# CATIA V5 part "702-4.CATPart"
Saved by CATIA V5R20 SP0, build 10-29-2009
Part number: 702-4
Source: Unknown
Property "ARTICLENO": "702-4"
Property "BOMINFO": "702-4"
Property "CODE": "702-4"
Property "L": "120.000"
Property "LINA": "702-4"
Property "NB": "702-4"
Property "NBSYN": "$CODE."
Property "NN": "702"
Property "SUPPLIER": "CF"
Bounding box of the stored display mesh (mm): x -107 to 0, y 0 to 120, z -15 to 15
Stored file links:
  C:\Users\Utente\Desktop\3D files 702\702-4.CATPart
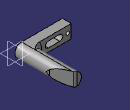
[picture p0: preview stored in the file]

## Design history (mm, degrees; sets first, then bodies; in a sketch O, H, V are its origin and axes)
Body1 "Geometry.1" (main body)
  Solid1 "702-4catpart": solid without history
